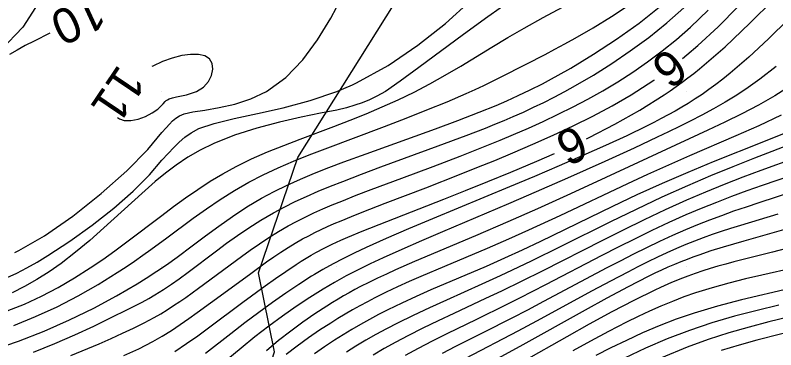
# Model space of a CAD drawing. Extents: x 2602990 to 2605851, y 618069 to 619180.
# Drawn here: x 2603301.63 to 2603345.08, y 618635.24 to 618654.36 of the extents above; entities that cross this region are included whole.
import ezdxf

# ---------------------------------------------------------------- set-up
doc = ezdxf.new("R2010")
doc.units = 0
for name, color, linetype in [('DTM Contours Major', 7, 'Continuous'), ('DTM Contours Minor', 7, 'Continuous'), ('DTM Contours Minor Text', 7, 'Continuous'), ('Exist DTM Crownline', 7, 'Continuous'), ('Exist DTM QL2 LIDAR Elevation Point', 7, 'Continuous'), ('Exist Roads EOP', 7, 'Continuous'), ('PH Exist DTM Obscure Area', 7, 'Continuous')]:
    doc.layers.add(name, color=color, linetype=linetype)

msp = doc.modelspace()

# ---------------------------------------------------------------- linework, layer by layer
at = {"layer": 'DTM Contours Major'}
for points in [[(2603330.027, 618655.274), (2603328.62, 618654.267), (2603327.229, 618653.248), (2603324.683, 618651.364), (2603323.625, 618650.593), (2603322.772, 618650), (2603322.294, 618649.738), (2603321.863, 618649.529), (2603321.449, 618649.359), (2603321.021, 618649.212), (2603320.548, 618649.072), (2603320, 618648.924)], [(2603345.925, 618650.322), (2603345.022, 618649.751), (2603344.091, 618649.22), (2603343.137, 618648.721), (2603342.169, 618648.245), (2603341.192, 618647.785), (2603334.834, 618644.837), (2603333.142, 618644.061), (2603331.456, 618643.3), (2603329.772, 618642.557), (2603327.923, 618641.762), (2603324.434, 618640.278), (2603323.352, 618639.806), (2603322.834, 618639.572), (2603322.328, 618639.336), (2603321.834, 618639.096), (2603321.349, 618638.85), (2603321.027, 618638.679), (2603320.707, 618638.504), (2603320.387, 618638.323), (2603320.068, 618638.136), (2603319.746, 618637.941), (2603319.423, 618637.738), (2603318.747, 618637.296), (2603318.06, 618636.818), (2603317.367, 618636.307), (2603316.673, 618635.765), (2603315.982, 618635.193)], [(2603320, 618648.924), (2603319.072, 618648.757), (2603317.954, 618648.532), (2603316.716, 618648.247), (2603315.426, 618647.903), (2603314.154, 618647.497), (2603312.97, 618647.03), (2603312.191, 618646.649), (2603311.482, 618646.238), (2603310.829, 618645.799), (2603310.216, 618645.337), (2603309.63, 618644.853), (2603309.057, 618644.352), (2603308.274, 618643.645), (2603306.691, 618642.203), (2603305.887, 618641.495), (2603305.071, 618640.814), (2603304.243, 618640.174), (2603303.559, 618639.693), (2603302.866, 618639.251), (2603302.161, 618638.852), (2603301.447, 618638.501)], [(2603346.123, 618639.921), (2603344.286, 618639.507), (2603343.34, 618639.288), (2603342.387, 618639.051), (2603341.435, 618638.789), (2603340.493, 618638.495), (2603339.828, 618638.261), (2603339.169, 618638.008), (2603338.514, 618637.737), (2603337.861, 618637.447), (2603337.207, 618637.14), (2603336.548, 618636.817), (2603335.526, 618636.293), (2603334.5, 618635.744), (2603333.479, 618635.182)]]:
    msp.add_lwpolyline(points, dxfattribs=at)
at = {"layer": 'DTM Contours Minor'}
for points in [[(2603311.271, 618648.729), (2603311.769, 618648.83), (2603312.453, 618648.935), (2603313.27, 618649.075), (2603314.167, 618649.279), (2603315.091, 618649.577), (2603315.988, 618650), (2603317.084, 618650.795), (2603318.05, 618651.801), (2603318.9, 618652.953), (2603319.648, 618654.181), (2603320.308, 618655.42)], [(2603312.12, 618647.88), (2603312.987, 618648.178), (2603314.126, 618648.454), (2603315.467, 618648.742), (2603316.939, 618649.073), (2603318.471, 618649.482), (2603319.992, 618650), (2603320.406, 618650.169), (2603320.889, 618650.383), (2603321.128, 618650.495), (2603322.93, 618651.483), (2603324.629, 618652.635), (2603326.202, 618653.889), (2603327.627, 618655.185)], [(2603334.258, 618647.301), (2603334.41, 618647.373), (2603335.881, 618648.123), (2603337.316, 618648.932), (2603338.702, 618649.807), (2603339.045, 618650.041), (2603339.384, 618650.281), (2603339.721, 618650.526), (2603340.054, 618650.776), (2603340.386, 618651.033), (2603340.716, 618651.297), (2603342.178, 618652.554), (2603343.598, 618653.894), (2603344.953, 618655.26)], [(2603300.355, 618635.25), (2603301.821, 618635.739), (2603303.288, 618636.314), (2603304.727, 618636.953), (2603306.109, 618637.63), (2603307.406, 618638.325), (2603308.589, 618639.013), (2603309.11, 618639.335), (2603309.716, 618639.728), (2603310.268, 618640.105), (2603310.877, 618640.539), (2603311.744, 618641.181), (2603312.497, 618641.746), (2603313.262, 618642.312), (2603314.048, 618642.867), (2603314.859, 618643.403), (2603315.702, 618643.907), (2603316.42, 618644.292), (2603317.164, 618644.654), (2603317.933, 618644.999), (2603318.729, 618645.33), (2603319.55, 618645.654), (2603320.397, 618645.974), (2603321.682, 618646.446), (2603325.642, 618647.87), (2603326.92, 618648.344), (2603328.139, 618648.815), (2603329.097, 618649.207), (2603329.716, 618649.474), (2603330.363, 618649.767), (2603331.046, 618650.094), (2603331.741, 618650.445), (2603332.097, 618650.632), (2603333.358, 618651.333), (2603334.665, 618652.122), (2603335.983, 618652.984), (2603337.279, 618653.909), (2603338.518, 618654.884)], [(2603301.172, 618637.462), (2603302.157, 618637.856), (2603303.129, 618638.308), (2603304.083, 618638.81), (2603305.013, 618639.351), (2603305.913, 618639.922), (2603306.629, 618640.408), (2603307.325, 618640.904), (2603308.006, 618641.407), (2603309.997, 618642.921), (2603310.677, 618643.429), (2603311.362, 618643.925), (2603312.057, 618644.406), (2603312.766, 618644.867), (2603313.493, 618645.304), (2603314.244, 618645.715), (2603315.124, 618646.144), (2603316.033, 618646.542), (2603316.964, 618646.918), (2603317.912, 618647.28), (2603319.83, 618647.996), (2603320.756, 618648.354), (2603321.677, 618648.726), (2603322.594, 618649.116), (2603323.505, 618649.529), (2603324.409, 618649.966), (2603325.305, 618650.432), (2603326.194, 618650.93), (2603327.079, 618651.452), (2603328.86, 618652.537), (2603329.767, 618653.084), (2603330.692, 618653.623), (2603331.786, 618654.228), (2603332.89, 618654.814)], [(2603301.538, 618636.634), (2603302.787, 618637.137), (2603304.02, 618637.706), (2603305.221, 618638.326), (2603306.372, 618638.98), (2603307.459, 618639.651), (2603307.961, 618639.98), (2603308.446, 618640.31), (2603308.919, 618640.64), (2603309.381, 618640.971), (2603310.288, 618641.637), (2603311.797, 618642.753), (2603312.563, 618643.301), (2603313.344, 618643.832), (2603314.148, 618644.34), (2603314.979, 618644.819), (2603315.799, 618645.241), (2603316.647, 618645.636), (2603317.522, 618646.012), (2603318.421, 618646.374), (2603319.342, 618646.729), (2603322.732, 618648.003), (2603323.954, 618648.472), (2603325.148, 618648.943), (2603326.296, 618649.414), (2603327.38, 618649.883), (2603327.895, 618650.116), (2603328.392, 618650.349), (2603329.348, 618650.814), (2603330.815, 618651.555), (2603331.901, 618652.118), (2603332.456, 618652.413), (2603333.024, 618652.721), (2603333.606, 618653.044), (2603334.64, 618653.641), (2603335.698, 618654.289), (2603336.75, 618654.987)], [(2603302.671, 618635.105), (2603303.881, 618635.595), (2603305.037, 618636.1), (2603306.121, 618636.6), (2603307.117, 618637.079), (2603308.044, 618637.539), (2603308.469, 618637.757), (2603308.871, 618637.971), (2603309.251, 618638.181), (2603309.611, 618638.389), (2603310.093, 618638.686), (2603310.551, 618638.989), (2603310.997, 618639.3), (2603311.502, 618639.669), (2603313.117, 618640.892), (2603313.703, 618641.329), (2603314.324, 618641.774), (2603314.976, 618642.219), (2603315.661, 618642.655), (2603316.378, 618643.073), (2603316.989, 618643.399), (2603317.62, 618643.71), (2603318.271, 618644.009), (2603318.942, 618644.3), (2603319.633, 618644.584), (2603320.342, 618644.866), (2603321.414, 618645.278), (2603322.509, 618645.688), (2603325.781, 618646.886), (2603327.387, 618647.484), (2603328.488, 618647.911), (2603329.022, 618648.126), (2603329.55, 618648.344), (2603330.073, 618648.568), (2603330.654, 618648.825), (2603331.235, 618649.094), (2603331.822, 618649.377), (2603332.416, 618649.677), (2603333.021, 618649.997), (2603333.64, 618650.34), (2603334.66, 618650.94), (2603335.707, 618651.601), (2603336.764, 618652.319), (2603337.815, 618653.091), (2603338.843, 618653.911), (2603339.831, 618654.777)], [(2603304.8, 618634.911), (2603306.416, 618635.592), (2603307.103, 618635.889), (2603307.761, 618636.184), (2603308.391, 618636.48), (2603308.99, 618636.779), (2603309.558, 618637.084), (2603309.943, 618637.306), (2603310.315, 618637.534), (2603310.676, 618637.765), (2603311.028, 618638.001), (2603311.373, 618638.24), (2603312.099, 618638.761), (2603314.544, 618640.573), (2603315.052, 618640.938), (2603315.573, 618641.299), (2603316.108, 618641.653), (2603316.658, 618641.996), (2603317.224, 618642.324), (2603317.701, 618642.579), (2603318.191, 618642.824), (2603318.693, 618643.061), (2603319.209, 618643.291), (2603319.739, 618643.517), (2603320.283, 618643.741), (2603321.108, 618644.069), (2603321.959, 618644.396), (2603323.715, 618645.055), (2603325.503, 618645.72), (2603327.036, 618646.304), (2603327.8, 618646.603), (2603328.562, 618646.908), (2603329.325, 618647.22), (2603330.089, 618647.54), (2603330.94, 618647.909), (2603331.792, 618648.292), (2603332.644, 618648.694), (2603333.496, 618649.118), (2603334.346, 618649.566), (2603335.194, 618650.042), (2603336.051, 618650.557), (2603336.902, 618651.106), (2603337.746, 618651.69), (2603338.579, 618652.313), (2603339.399, 618652.976), (2603340.205, 618653.682), (2603341.204, 618654.641)], [(2603339.74, 618651.875), (2603339.999, 618652.085), (2603340.62, 618652.617), (2603341.784, 618653.7), (2603342.926, 618654.859)], [(2603345.805, 618654.13), (2603344.656, 618653.01), (2603343.538, 618651.967), (2603342.467, 618651.036), (2603342.058, 618650.706), (2603341.657, 618650.396), (2603341.26, 618650.106), (2603340.865, 618649.831), (2603340.471, 618649.57), (2603340.073, 618649.319), (2603339.7, 618649.095), (2603339.319, 618648.876), (2603338.93, 618648.661), (2603338.53, 618648.447), (2603338.116, 618648.234), (2603337.686, 618648.018), (2603336.559, 618647.474), (2603335.34, 618646.912), (2603334.046, 618646.334), (2603332.692, 618645.745), (2603331.295, 618645.15), (2603329.872, 618644.553), (2603325.461, 618642.722), (2603324.094, 618642.146), (2603322.823, 618641.598), (2603321.674, 618641.085), (2603320.981, 618640.761), (2603320.341, 618640.446), (2603319.792, 618640.159), (2603319.202, 618639.83), (2603318.718, 618639.543), (2603318.555, 618639.444), (2603317.829, 618638.981), (2603317.082, 618638.478), (2603316.317, 618637.94), (2603315.537, 618637.371), (2603314.744, 618636.776), (2603313.942, 618636.158), (2603312.503, 618635.039)], [(2603303.599, 618653.324), (2603302.7, 618652.88), (2603302.203, 618652.622), (2603301.739, 618652.366), (2603301.308, 618652.108)], [(2603310.421, 618649.579), (2603310.604, 618649.644), (2603310.842, 618649.699), (2603311.411, 618649.815), (2603311.706, 618649.894), (2603311.984, 618650), (2603312.374, 618650.249), (2603312.662, 618650.565), (2603312.845, 618650.916), (2603312.918, 618651.27), (2603312.88, 618651.595), (2603312.726, 618651.856), (2603312.458, 618652.03), (2603312.091, 618652.116), (2603311.646, 618652.119), (2603311.142, 618652.047), (2603310.6, 618651.907), (2603310.04, 618651.703), (2603309.479, 618651.443), (2603309.439, 618651.421)], [(2603345.099, 618651.42), (2603344.17, 618650.696), (2603343.506, 618650.224), (2603342.844, 618649.79), (2603342.182, 618649.387), (2603341.52, 618649.01), (2603340.856, 618648.652), (2603340.191, 618648.308), (2603339.57, 618647.997), (2603338.943, 618647.689), (2603338.306, 618647.384), (2603336.991, 618646.77), (2603335.301, 618645.999), (2603333.18, 618645.051), (2603330.95, 618644.076), (2603329.809, 618643.585), (2603326.041, 618641.986), (2603324.845, 618641.474), (2603323.71, 618640.978), (2603322.653, 618640.502), (2603321.91, 618640.155), (2603321.209, 618639.812), (2603320.537, 618639.463), (2603319.874, 618639.097), (2603319.212, 618638.706), (2603318.453, 618638.231), (2603317.681, 618637.717), (2603316.898, 618637.168), (2603316.111, 618636.588), (2603315.322, 618635.979), (2603314.536, 618635.344), (2603313.773, 618634.704)], [(2603307.84, 618634.909), (2603308.68, 618635.303), (2603309.481, 618635.719), (2603310.024, 618636.031), (2603310.546, 618636.354), (2603311.051, 618636.685), (2603311.542, 618637.023), (2603312.021, 618637.365), (2603313.547, 618638.485), (2603315.078, 618639.611), (2603315.988, 618640.262), (2603316.397, 618640.545), (2603316.806, 618640.819), (2603317.215, 618641.082), (2603317.628, 618641.334), (2603318.045, 618641.573), (2603318.392, 618641.76), (2603318.745, 618641.94), (2603319.105, 618642.114), (2603319.473, 618642.284), (2603319.851, 618642.451), (2603320.239, 618642.617), (2603320.83, 618642.86), (2603321.446, 618643.106), (2603322.754, 618643.61), (2603325.078, 618644.497), (2603327.002, 618645.249), (2603328.001, 618645.648), (2603329.018, 618646.062), (2603330.047, 618646.49), (2603331.2, 618646.983), (2603332.355, 618647.494), (2603333.501, 618648.029), (2603334.631, 618648.59), (2603335.735, 618649.18), (2603336.806, 618649.803), (2603337.467, 618650.218), (2603338.114, 618650.651), (2603338.142, 618650.672)], [(2603307.477, 618648.515), (2603307.586, 618648.429), (2603307.854, 618648.342), (2603308.227, 618648.34), (2603308.643, 618648.425), (2603309.065, 618648.575), (2603309.456, 618648.772), (2603309.78, 618648.994), (2603310, 618649.221), (2603310.071, 618649.29), (2603310.192, 618649.419), (2603310.255, 618649.478), (2603310.329, 618649.531), (2603310.421, 618649.579)], [(2603301.613, 618640.81), (2603301.832, 618640.912), (2603303.303, 618641.75), (2603304.915, 618642.877), (2603306.529, 618644.162), (2603308.007, 618645.473), (2603309.21, 618646.679), (2603310, 618647.649), (2603310.246, 618647.913), (2603310.444, 618648.135), (2603310.619, 618648.32), (2603310.798, 618648.477), (2603311.006, 618648.611), (2603311.271, 618648.729)], [(2603345.382, 618648.651), (2603344.101, 618648.043), (2603342.792, 618647.46), (2603340.15, 618646.323), (2603338.942, 618645.789), (2603337.756, 618645.251), (2603336.599, 618644.716), (2603332.735, 618642.901), (2603330.947, 618642.075), (2603329.812, 618641.566), (2603328.583, 618641.031), (2603326.154, 618640.002), (2603324.807, 618639.43), (2603324.137, 618639.138), (2603323.473, 618638.838), (2603322.816, 618638.53), (2603322.17, 618638.212), (2603321.743, 618637.991), (2603321.32, 618637.764), (2603320.901, 618637.529), (2603320.483, 618637.287), (2603320.066, 618637.035), (2603319.649, 618636.774), (2603319.013, 618636.358), (2603318.375, 618635.92), (2603317.739, 618635.458), (2603317.106, 618634.974)], [(2603301.164, 618639.378), (2603301.715, 618639.63), (2603302.287, 618639.923), (2603302.88, 618640.256), (2603303.495, 618640.627), (2603304.75, 618641.452), (2603306.024, 618642.371), (2603307.252, 618643.339), (2603308.367, 618644.31), (2603309.305, 618645.238), (2603310, 618646.076), (2603310.373, 618646.454), (2603310.693, 618646.796), (2603310.993, 618647.106), (2603311.308, 618647.388), (2603311.673, 618647.645), (2603312.12, 618647.88)], [(2603345.752, 618647.684), (2603344.381, 618647.124), (2603341.507, 618645.983), (2603340.043, 618645.38), (2603338.579, 618644.743), (2603337.142, 618644.086), (2603335.748, 618643.427), (2603334.416, 618642.783), (2603331.636, 618641.429), (2603330.594, 618640.934), (2603329.582, 618640.47), (2603328.526, 618640.005), (2603325.371, 618638.66), (2603324.541, 618638.294), (2603323.717, 618637.916), (2603322.91, 618637.525), (2603322.381, 618637.255), (2603321.862, 618636.978), (2603321.353, 618636.694), (2603320.851, 618636.402), (2603320.356, 618636.101), (2603319.867, 618635.792), (2603319.293, 618635.413), (2603318.725, 618635.02)], [(2603346.186, 618647.083), (2603343.861, 618646.183), (2603342.619, 618645.694), (2603341.339, 618645.173), (2603340.033, 618644.617), (2603338.565, 618643.955), (2603337.093, 618643.261), (2603335.633, 618642.55), (2603332.802, 618641.146), (2603331.094, 618640.307), (2603330.023, 618639.796), (2603329.322, 618639.468), (2603328.287, 618638.995), (2603326.268, 618638.087), (2603325.296, 618637.645), (2603324.357, 618637.204), (2603323.456, 618636.762), (2603322.834, 618636.44), (2603322.233, 618636.115), (2603321.653, 618635.786), (2603321.09, 618635.452), (2603320.544, 618635.113)], [(2603310.749, 618635.15), (2603311.411, 618635.594), (2603312.052, 618636.047), (2603312.675, 618636.503), (2603314.63, 618637.959), (2603315.904, 618638.89), (2603316.505, 618639.318), (2603317.078, 618639.716), (2603317.674, 618640.115), (2603317.961, 618640.3), (2603318.245, 618640.476), (2603318.526, 618640.644), (2603318.806, 618640.804), (2603319.268, 618641.05), (2603319.741, 618641.283), (2603320.237, 618641.509), (2603320.619, 618641.675), (2603321.441, 618642.014), (2603322.851, 618642.57), (2603326.119, 618643.846), (2603327.35, 618644.335), (2603328.629, 618644.85), (2603329.942, 618645.389), (2603331.426, 618646.014), (2603332.443, 618646.462)], [(2603346.216, 618646.217), (2603344.228, 618645.488), (2603343.191, 618645.097), (2603342.132, 618644.685), (2603341.058, 618644.25), (2603339.973, 618643.787), (2603338.761, 618643.242), (2603337.552, 618642.67), (2603336.354, 618642.084), (2603335.176, 618641.494), (2603331.721, 618639.738), (2603330.56, 618639.16), (2603329.407, 618638.601), (2603328.5, 618638.172), (2603326.685, 618637.326), (2603325.79, 618636.904), (2603324.914, 618636.479), (2603324.063, 618636.049), (2603323.376, 618635.684), (2603322.711, 618635.315), (2603322.069, 618634.942)], [(2603346.808, 618645.492), (2603344.295, 618644.627), (2603343.425, 618644.318), (2603342.554, 618643.998), (2603341.682, 618643.664), (2603340.81, 618643.315), (2603339.937, 618642.947), (2603338.967, 618642.514), (2603337.999, 618642.06), (2603337.035, 618641.59), (2603336.078, 618641.109), (2603335.13, 618640.623), (2603331.927, 618638.955), (2603330.432, 618638.19), (2603329.682, 618637.814), (2603327.973, 618636.982), (2603326.282, 618636.159), (2603325.455, 618635.745), (2603324.648, 618635.326), (2603323.897, 618634.918)], [(2603346.029, 618644.258), (2603344.107, 618643.638), (2603343.379, 618643.396), (2603342.666, 618643.153), (2603341.968, 618642.904), (2603341.28, 618642.649), (2603340.601, 618642.383), (2603339.927, 618642.104), (2603339.182, 618641.778), (2603338.437, 618641.435), (2603337.691, 618641.076), (2603336.941, 618640.702), (2603336.185, 618640.315), (2603335.421, 618639.916), (2603331.815, 618637.996), (2603330.901, 618637.515), (2603329.989, 618637.042), (2603328.37, 618636.225), (2603326.784, 618635.425), (2603326.009, 618635.024)], [(2603345.189, 618642.988), (2603343.053, 618642.346), (2603342.497, 618642.172), (2603341.96, 618641.998), (2603341.439, 618641.821), (2603340.931, 618641.64), (2603340.433, 618641.453), (2603339.942, 618641.259), (2603339.4, 618641.031), (2603338.858, 618640.79), (2603338.312, 618640.536), (2603337.76, 618640.268), (2603337.196, 618639.985), (2603336.617, 618639.687), (2603335.625, 618639.164), (2603334.595, 618638.61), (2603331.397, 618636.873), (2603330.337, 618636.307), (2603327.359, 618634.752)], [(2603345.782, 618642.17), (2603343.242, 618641.454), (2603342.078, 618641.113), (2603341.363, 618640.889), (2603340.679, 618640.656), (2603340.344, 618640.535), (2603340.013, 618640.41), (2603339.648, 618640.265), (2603339.283, 618640.113), (2603338.916, 618639.954), (2603338.546, 618639.787), (2603338.171, 618639.612), (2603337.788, 618639.427), (2603336.635, 618638.844), (2603335.426, 618638.2), (2603334.181, 618637.516), (2603330.451, 618635.43), (2603327.031, 618633.56)], [(2603346.046, 618641.13), (2603344.88, 618640.827), (2603343.749, 618640.54), (2603342.672, 618640.262), (2603342.215, 618640.138), (2603341.769, 618640.012), (2603341.331, 618639.882), (2603340.9, 618639.747), (2603340.473, 618639.603), (2603340.046, 618639.451), (2603339.739, 618639.334), (2603339.119, 618639.082), (2603338.484, 618638.804), (2603338.158, 618638.653), (2603336.963, 618638.068), (2603335.709, 618637.411), (2603334.423, 618636.709), (2603333.131, 618635.986), (2603330.638, 618634.576)], [(2603345.873, 618638.753), (2603343.117, 618638.096), (2603341.744, 618637.739), (2603340.404, 618637.341), (2603339.39, 618636.991), (2603338.41, 618636.61), (2603337.461, 618636.206), (2603336.544, 618635.783), (2603335.659, 618635.349), (2603334.804, 618634.909)], [(2603345.246, 618637.801), (2603344.004, 618637.497), (2603342.726, 618637.161), (2603341.43, 618636.782), (2603340.137, 618636.351), (2603338.868, 618635.862), (2603337.632, 618635.327), (2603336.441, 618634.763)], [(2603345.775, 618637.101), (2603344.688, 618636.832), (2603343.56, 618636.538), (2603342.398, 618636.208), (2603341.213, 618635.833), (2603340.013, 618635.401), (2603338.545, 618634.792)], [(2603346.699, 618636.487), (2603344, 618635.788), (2603342.983, 618635.508), (2603341.949, 618635.199)]]:
    msp.add_lwpolyline(points, dxfattribs=at)
at = {"layer": 'Exist DTM Crownline'}
msp.add_spline([(2603233.488, 618380.754), (2603285.185, 618400.095), (2603335.457, 618418.629), (2603390.812, 618439.069), (2603440.087, 618457.325), (2603493.996, 618477.231), (2603542.655, 618495.301), (2603600.808, 618516.867), (2603653.659, 618536.362), (2603706.222, 618555.742), (2603764.811, 618577.593), (2603823.52, 618599.847), (2603878.564, 618620.56), (2603937.951, 618643.078), (2603997.369, 618665.789), (2604036.209, 618680.665), (2604055.311, 618688.017)], degree=3, dxfattribs=at)
at = {"layer": 'Exist DTM QL2 LIDAR Elevation Point'}
for p, q in [((2603310, 618650), (2603310, 618650)), ((2603320, 618650), (2603320, 618650)), ((2603330, 618650), (2603330, 618650)), ((2603340, 618650), (2603340, 618650)), ((2603310, 618640), (2603310, 618640)), ((2603320, 618640), (2603320, 618640)), ((2603330, 618640), (2603330, 618640)), ((2603340, 618640), (2603340, 618640))]:
    msp.add_line(p, q, dxfattribs=at)
at = {"layer": 'Exist Roads EOP'}
for points in [[(2603230.17, 618389.98), (2603282.929, 618409.597), (2603332.773, 618427.868), (2603388.167, 618448.413), (2603437.203, 618466.721), (2603490.778, 618486.527), (2603539.039, 618504.558), (2603597.451, 618526.156), (2603651.053, 618545.972), (2603705.208, 618566.084), (2603762.02, 618587.183), (2603820.334, 618609.162), (2603876.341, 618629.99), (2603934.909, 618652.28), (2603996.409, 618675.568), (2604033.216, 618689.957), (2604052.01, 618697.199)], [(2604034.633, 618668.486), (2603984.89, 618650.123), (2603936.767, 618631.654), (2603888.195, 618613.335), (2603837.766, 618594.258), (2603782.918, 618573.705), (2603731.939, 618554.39), (2603671.126, 618532.171), (2603621.822, 618514.106), (2603561.545, 618491.877), (2603506.421, 618471.293), (2603452.163, 618451.33), (2603398.364, 618431.316), (2603341.431, 618410.355), (2603281.65, 618388.199), (2603223.033, 618366.475), (2603185.717, 618352.612)]]:
    msp.add_spline(points, degree=3, dxfattribs=at)
at = {"layer": 'PH Exist DTM Obscure Area'}
for points in [[(2603265.087, 618589.76), (2603272.976, 618594.164), (2603276.671, 618597.191), (2603280.942, 618601.168), (2603285.34, 618605.272), (2603290.685, 618608.482), (2603298.066, 618612.825), (2603304.621, 618616.727), (2603312.647, 618623.288), (2603316.448, 618635.135), (2603315.518, 618639.645), (2603317.77, 618646.233), (2603324.356, 618656.735), (2603336.075, 618665.816), (2603339.207, 618670.496), (2603343.226, 618674.918), (2603351.998, 618678.303)], [(2603312.275, 618674.534), (2603312.005, 618674.434), (2603311.545, 618671.137), (2603310.068, 618667.527), (2603307.195, 618663.797), (2603305.011, 618658.287), (2603302.07, 618653.669), (2603297.096, 618648.49), (2603293.652, 618645.017), (2603291.728, 618640.711), (2603294.249, 618637.146), (2603297.906, 618632.306), (2603295.34, 618626.544), (2603289.815, 618625.428), (2603280.616, 618625.917), (2603273.497, 618623.286), (2603273.419, 618620.24), (2603273.077, 618615.166), (2603270.508, 618608.643), (2603262.367, 618604.748)]]:
    msp.add_lwpolyline(points, dxfattribs=at)

# ---------------------------------------------------------------- texts
at = {"layer": 'DTM Contours Minor Text'}
for s, rotation, p in [('10', 204.8145, (2603306.169, 618655.625)), ('9', 36.991, (2603339.032, 618650.067)), ('11', 235.9618, (2603307.535, 618651.609)), ('9', 24.8176, (2603333.18, 618645.694))]:
    msp.add_text(s, height=2, rotation=rotation, dxfattribs=at).set_placement(p)

doc.saveas('drawing.dxf')
